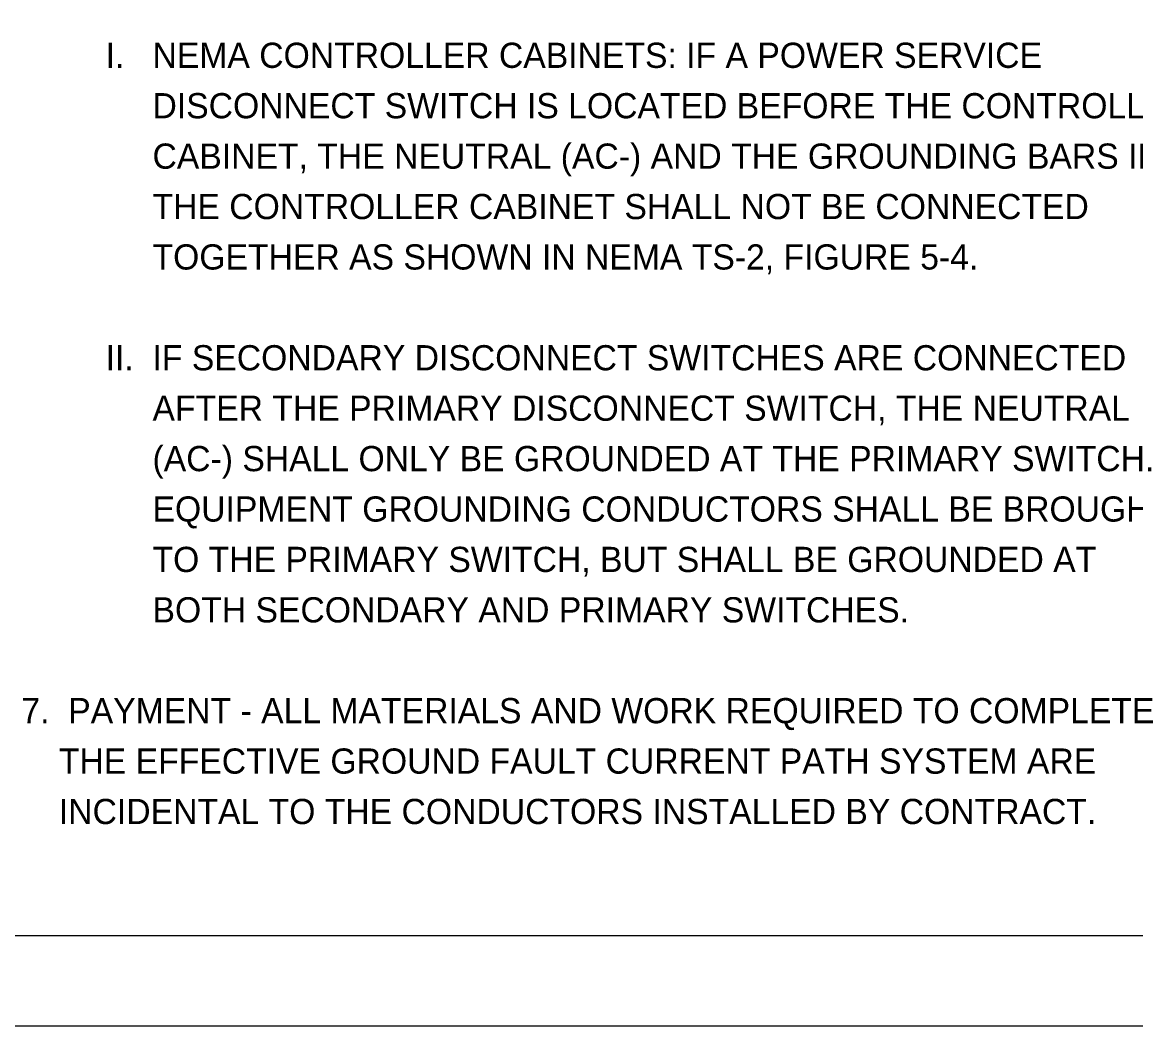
# Model space of a CAD drawing. Extents: x 0 to 34, y 0 to 22.
# Drawn here: x 24.66 to 30.85, y 0 to 5.57 of the extents above; entities that cross this region are included whole.
import ezdxf

# ---------------------------------------------------------------- set-up
doc = ezdxf.new("R2010")
doc.units = 0
for name, color, linetype in [('SH_Border', 7, 'Continuous'), ('SH_Cut_Line', 7, 'Continuous'), ('SH_Text', 7, 'Continuous')]:
    doc.layers.add(name, color=color, linetype=linetype)

msp = doc.modelspace()

# ---------------------------------------------------------------- linework, layer by layer
at = {"layer": 'SH_Border'}
msp.add_lwpolyline([(1.5, 21.5), (33.5, 21.5), (33.5, 0.5), (1.5, 0.5)], close=True, dxfattribs=at)
at = {"layer": 'SH_Cut_Line'}
msp.add_lwpolyline([(0, 0), (34, 0), (34, 22), (0, 22)], close=True, dxfattribs=at)

# ---------------------------------------------------------------- texts
at = {"layer": 'SH_Text'}
for s, p in [('         I.   NEMA CONTROLLER CABINETS: IF A POWER SERVICE', (24.66, 5.32)), ('              DISCONNECT SWITCH IS LOCATED BEFORE THE CONTROLLER ', (24.66, 5.04)), ('              CABINET, THE NEUTRAL (AC-) AND THE GROUNDING BARS IN ', (24.66, 4.76)), ('              THE CONTROLLER CABINET SHALL NOT BE CONNECTED ', (24.66, 4.48)), ('              TOGETHER AS SHOWN IN NEMA TS-2, FIGURE 5-4.', (24.66, 4.2)), ('         II.  IF SECONDARY DISCONNECT SWITCHES ARE CONNECTED', (24.66, 3.64)), ('              AFTER THE PRIMARY DISCONNECT SWITCH, THE NEUTRAL', (24.66, 3.36)), ('              (AC-) SHALL ONLY BE GROUNDED AT THE PRIMARY SWITCH. ', (24.66, 3.08)), ('              EQUIPMENT GROUNDING CONDUCTORS SHALL BE BROUGHT ', (24.66, 2.8)), ('              TO THE PRIMARY SWITCH, BUT SHALL BE GROUNDED AT ', (24.66, 2.52)), ('              BOTH SECONDARY AND PRIMARY SWITCHES.', (24.66, 2.24)), ('7.  PAYMENT - ALL MATERIALS AND WORK REQUIRED TO COMPLETE ', (24.66, 1.68)), ('    THE EFFECTIVE GROUND FAULT CURRENT PATH SYSTEM ARE ', (24.66, 1.4)), ('    INCIDENTAL TO THE CONDUCTORS INSTALLED BY CONTRACT.', (24.66, 1.12))]:
    msp.add_text(s, height=0.14, dxfattribs=at).set_placement(p)

doc.saveas('drawing.dxf')
